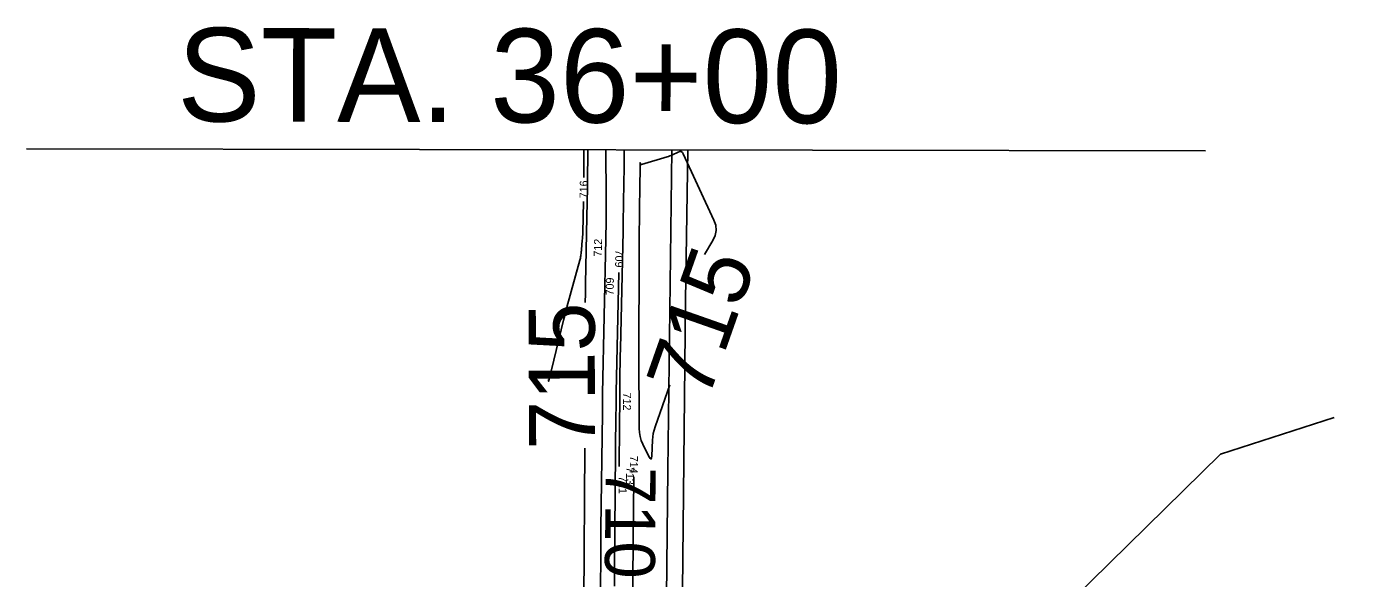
# Model space of a CAD drawing. Extents: x -468548933 to 3387700, y -306089263 to 1207014.
# Drawn here: x 1834950 to 1835612, y 537776 to 538052 of the extents above; entities that cross this region are included whole.
import ezdxf

# ---------------------------------------------------------------- set-up
doc = ezdxf.new("R2010")
doc.units = 0
for name, color, linetype in [('DT_X_Contour_Minor', 7, 'Continuous'), ('DT_X_Terrain_Ground_Line', 7, 'Continuous'), ('Level 19', 7, 'Continuous'), ('Level 40', 7, 'Continuous'), ('Level 56', 7, 'Continuous')]:
    doc.layers.add(name, color=color, linetype=linetype)

msp = doc.modelspace()

# ---------------------------------------------------------------- linework, layer by layer
at = {"layer": 'DT_X_Contour_Minor'}
for points in [[(1835228.63, 537976.22), (1835228.64, 537977.64), (1835228.66, 537981.44), (1835228.7, 537990.03)], [(1835229.3, 537913.62), (1835229.4, 537918.21), (1835229.42, 537919.4), (1835229.45, 537920.6), (1835229.47, 537921.79), (1835229.5, 537922.99), (1835230.2, 537956.52), (1835230.34, 537963.71), (1835230.44, 537970.9), (1835230.51, 537978.09), (1835230.56, 537985.27), (1835230.58, 537990.03)], [(1835236.95, 537770.36), (1835237.07, 537786.75), (1835237.09, 537790.26), (1835237.13, 537793.77), (1835237.16, 537797.28), (1835237.2, 537800.79), (1835237.9, 537858.06), (1835237.91, 537859.06), (1835237.92, 537860.06), (1835237.92, 537861.07), (1835237.92, 537862.07), (1835237.91, 537865.34), (1835237.91, 537866.04), (1835237.91, 537866.74), (1835237.92, 537867.44), (1835237.94, 537868.14), (1835239.62, 537945.55), (1835239.64, 537946.78), (1835239.67, 537948.01), (1835239.7, 537949.24), (1835239.72, 537950.47), (1835239.81, 537954.48), (1835239.82, 537955.34), (1835239.83, 537956.2), (1835239.84, 537957.06), (1835239.85, 537957.93), (1835239.87, 537962.33), (1835239.87, 537963.28), (1835239.86, 537964.22), (1835239.86, 537965.16), (1835239.85, 537966.11), (1835239.55, 537989.97)], [(1835248.82, 537989.86), (1835248.79, 537987.09), (1835248.75, 537984.32), (1835248.72, 537981.55), (1835248.49, 537964.11), (1835248.43, 537960.37), (1835248.37, 537956.64), (1835248.3, 537952.9), (1835248.22, 537949.17), (1835246.89, 537890.69), (1835246.81, 537886.84), (1835246.74, 537883), (1835246.69, 537879.15), (1835246.66, 537875.3), (1835246.57, 537862.73), (1835246.55, 537860.04), (1835246.53, 537857.35), (1835246.51, 537854.65), (1835246.48, 537851.96), (1835246.31, 537831.56)], [(1835288.89, 537937.63), (1835293.09, 537944.6), (1835294.25, 537947.11), (1835294.73, 537949.65), (1835294.53, 537952.23), (1835293.65, 537954.85), (1835278.35, 537987.95), (1835277.88, 537988.67), (1835277.29, 537989.07), (1835276.59, 537989.13), (1835275.77, 537988.87), (1835272.89, 537987.48), (1835272.27, 537987.19), (1835271.63, 537986.93), (1835270.99, 537986.7), (1835270.34, 537986.49), (1835257.38, 537982.64), (1835257.22, 537982.62), (1835257.09, 537982.66), (1835257, 537982.75), (1835256.93, 537982.9), (1835256.78, 537983.49), (1835256.75, 537983.58), (1835256.73, 537983.61), (1835256.72, 537983.58), (1835256.71, 537983.48), (1835256.57, 537968.91), (1835256.56, 537968.72), (1835256.56, 537968.52), (1835256.56, 537968.33), (1835256.56, 537968.13), (1835256.55, 537967.49), (1835256.55, 537967.36), (1835256.54, 537967.22), (1835256.54, 537967.08), (1835256.54, 537966.95), (1835256.49, 537964.93), (1835256.48, 537964.5), (1835256.48, 537964.07), (1835256.47, 537963.63), (1835256.47, 537963.2)], [(1835210.99, 537875.16), (1835211.01, 537874.4), (1835211.02, 537874.28), (1835211.04, 537874.24), (1835211.07, 537874.28), (1835211.1, 537874.39), (1835218.5, 537904.72), (1835219.4, 537908.33), (1835220.33, 537911.94), (1835221.29, 537915.53), (1835222.28, 537919.12), (1835226.67, 537934.81), (1835226.81, 537935.33), (1835226.92, 537935.86), (1835227.02, 537936.4), (1835227.09, 537936.94), (1835227.3, 537938.7), (1835227.35, 537939.08), (1835227.39, 537939.46), (1835227.43, 537939.84), (1835227.46, 537940.21), (1835227.88, 537944.66), (1835227.96, 537945.62), (1835228.03, 537946.57), (1835228.07, 537947.53), (1835228.1, 537948.48), (1835228.43, 537964.22)], [(1835256.47, 537963.2), (1835256.31, 537941.07), (1835256.27, 537936.14), (1835256.25, 537931.21), (1835256.23, 537926.28), (1835256.21, 537921.35), (1835256.17, 537903.83), (1835256.17, 537900.08), (1835256.17, 537896.33), (1835256.17, 537892.57), (1835256.18, 537888.82), (1835256.3, 537850.62), (1835256.42, 537848.56), (1835256.77, 537846.56), (1835257.35, 537844.6), (1835258.15, 537842.71), (1835261.16, 537836.59), (1835261.73, 537835.63), (1835262.16, 537835.35), (1835262.44, 537835.78), (1835262.58, 537836.89), (1835262.94, 537844.79), (1835263.08, 537846.47), (1835263.34, 537848.12), (1835263.72, 537849.76), (1835264.23, 537851.37), (1835271.68, 537872.41)], [(1835246.17, 537928.7), (1835244.81, 537868.76), (1835244.79, 537867.77), (1835244.77, 537866.78), (1835244.76, 537865.79), (1835244.75, 537864.8), (1835244.73, 537861.57), (1835244.72, 537860.88), (1835244.71, 537860.18), (1835244.71, 537859.49), (1835244.7, 537858.8), (1835244.02, 537779.62), (1835244.01, 537779.29), (1835244.01, 537778.96), (1835244, 537778.63), (1835243.99, 537778.3), (1835243.97, 537777.22), (1835243.96, 537776.99), (1835243.96, 537776.75), (1835243.95, 537776.52), (1835243.95, 537776.29), (1835243.9, 537771.72)], [(1835228.59, 537764.06), (1835229.14, 537840.75)], [(1835253.59, 537826.49), (1835252.72, 537742.53), (1835252.69, 537742.17), (1835252.62, 537741.83), (1835252.49, 537741.51), (1835252.32, 537741.2), (1835251.69, 537740.2), (1835251.57, 537739.98), (1835251.49, 537739.75), (1835251.43, 537739.52), (1835251.41, 537739.27), (1835251.2, 537726.2), (1835251.17, 537723.4), (1835251.14, 537720.6), (1835251.12, 537717.79), (1835251.12, 537714.99), (1835251.35, 537576.81)]]:
    msp.add_lwpolyline(points, dxfattribs=at)
at = {"layer": 'DT_X_Terrain_Ground_Line'}
msp.add_line((1835539.33, 537989.48), (1834950.07, 537990.5), dxfattribs=at)
at = {"layer": 'Level 40'}
msp.add_lwpolyline([(1835269.4, 537565.22), (1835546.87, 537837.73), (1835603.69, 537856.17)], dxfattribs=at)
at = {"layer": 'Level 56'}
for points in [[(1835272.54, 537989.9), (1835270.63, 537829.71), (1835268.58, 537639.91), (1835267.46, 537489.92), (1835266.63, 537389.92), (1835264.41, 537189.93), (1835263.9, 537104.93), (1835263.77, 536939.93), (1835262.99, 536824.67)], [(1835271.56, 536827.69), (1835271.95, 537089.9), (1835273.57, 537289.9), (1835275.29, 537464.69), (1835276.71, 537656.89), (1835279.46, 537914.68), (1835280.54, 537989.88)]]:
    msp.add_lwpolyline(points, dxfattribs=at)

# ---------------------------------------------------------------- texts
at = {"layer": 'DT_X_Terrain_Ground_Line'}
msp.add_text('STA. 36+00', height=46.8, rotation=359.82907, dxfattribs=at).set_placement((1835025.31, 538004.23))
at = {"layer": 'Level 19'}
for s, height, rotation, p in [('716', 4, 89.07581, (1835230.48, 537965.71)), ('712', 4, 88.78797, (1835237.57, 537936.52)), ('709', 4, 268.70015, (1835244.43, 537940.11)), ('715', 33, 70.63544, (1835290.38, 537863.77)), ('709', 4, 89.44244, (1835243.55, 537917.16)), ('715', 33, 90.15544, (1835234.24, 537840.03)), ('712', 4, 269.58128, (1835248.28, 537868.59)), ('714', 4, 269.4042, (1835251.7, 537836.99)), ('710', 25, 269.50207, (1835239.57, 537831.4)), ('711', 4, 269.50207, (1835246.1, 537826.88)), ('713', 4, 269.40885, (1835249.82, 537831.41))]:
    msp.add_text(s, height=height, rotation=rotation, dxfattribs=at).set_placement(p)
at = {"layer": 'Level 40'}
msp.add_text("OUTFALL 'M'", height=46.8, rotation=17.9864, dxfattribs=at).set_placement((1835526.17, 537640.31))

doc.saveas('drawing.dxf')
